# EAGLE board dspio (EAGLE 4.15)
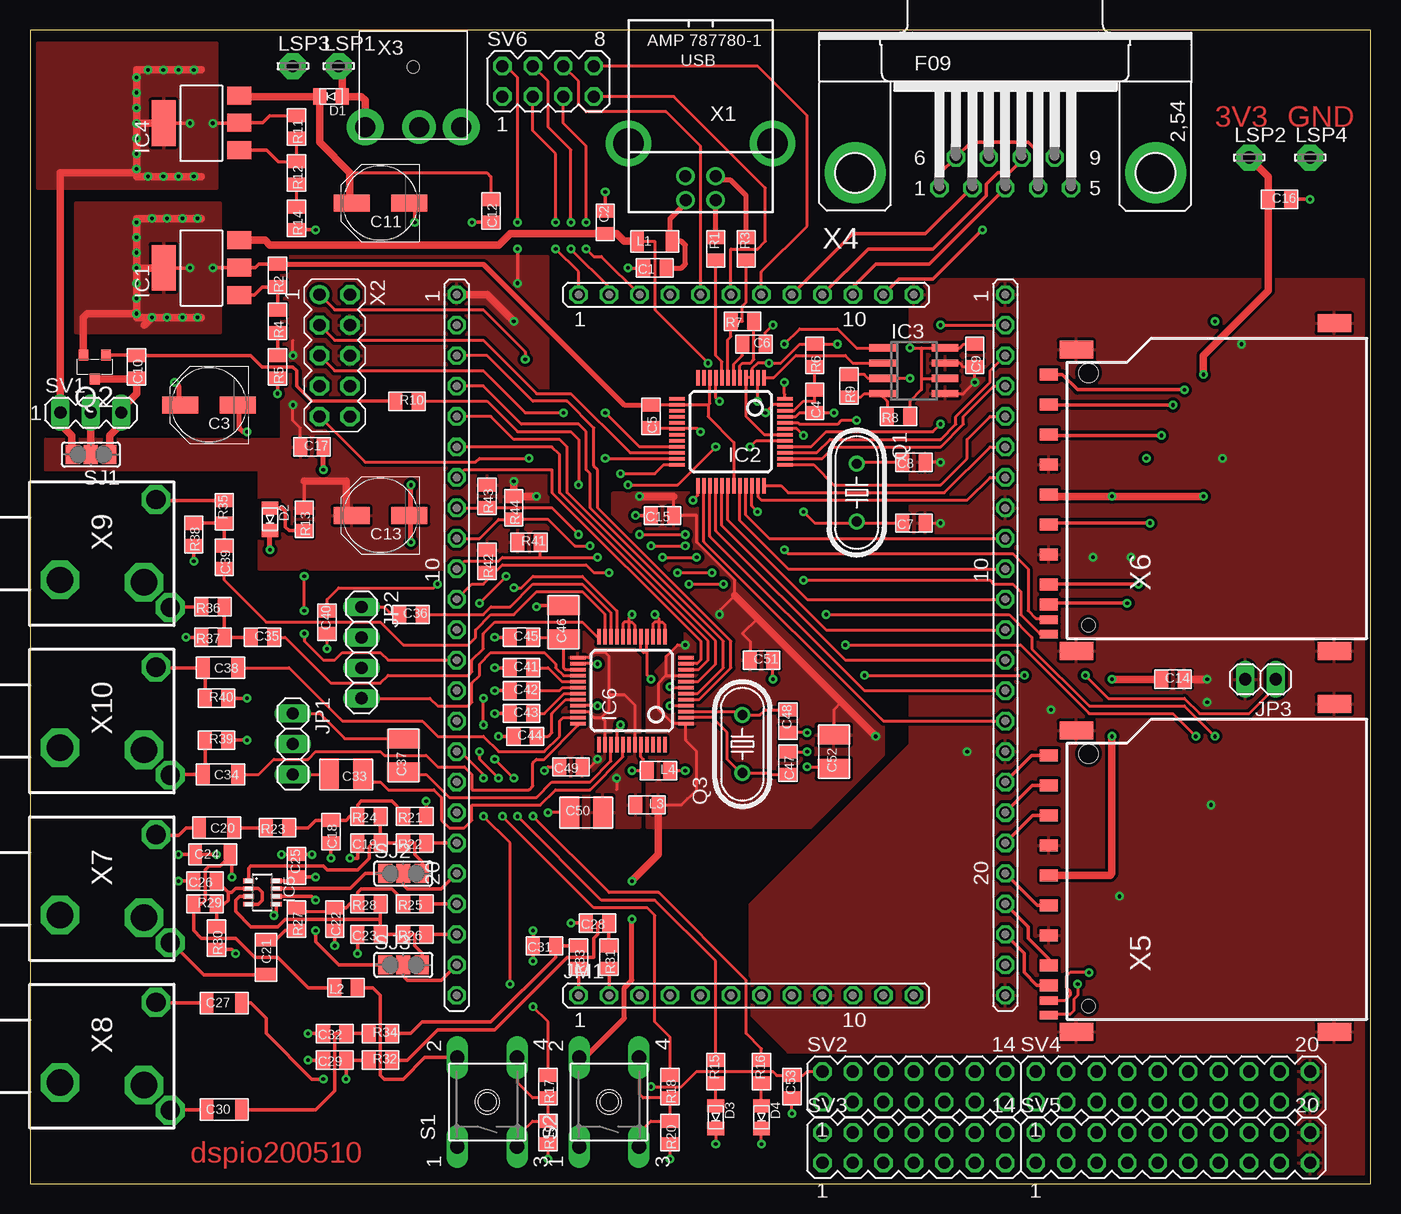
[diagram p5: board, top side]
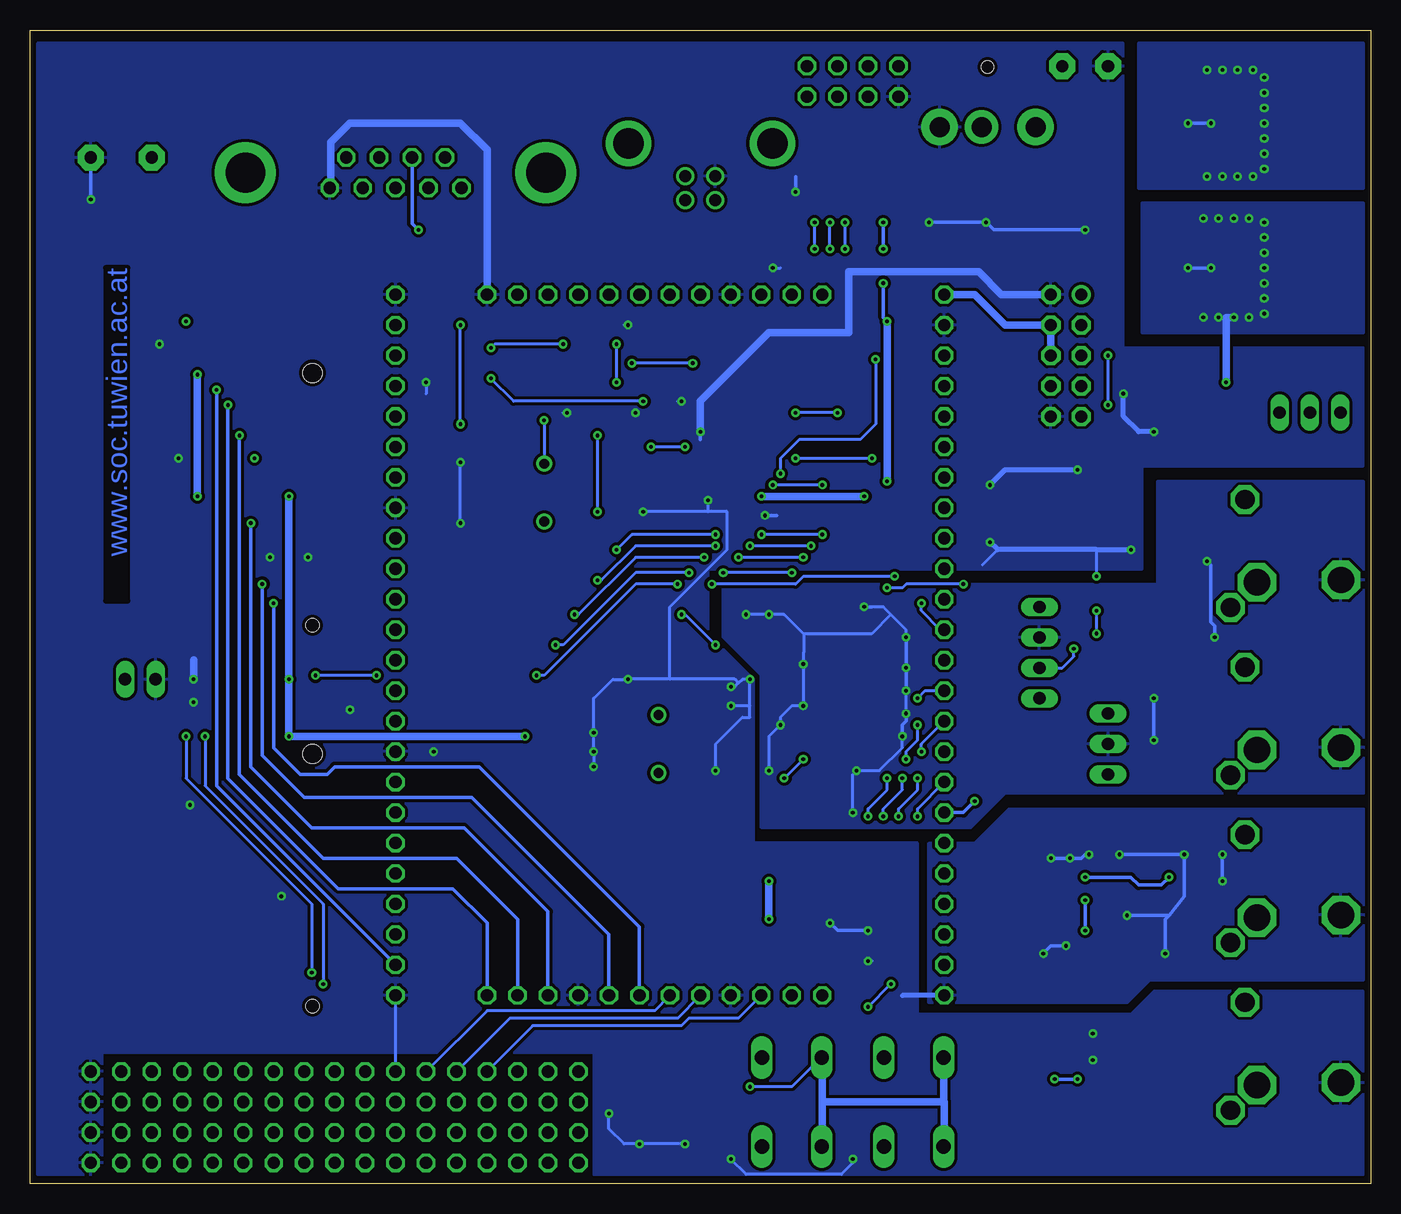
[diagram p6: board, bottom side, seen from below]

Size 111.74 x 96.19 mm. Coordinates in mm from the lower left corner, seen from the top.
Outline: 0,0 111.74,0 111.74,96.19 0,96.19 0,0
Copper layers (1*16): Top 0.035mm / dielectric 1.5mm / Bottom 0.035mm
Design rules "default": minimum track width 7mil, minimum drill 12mil, track to track 7mil, track to pad 8mil, pad to pad 8mil, via to via 8mil, smd to smd 8mil, copper to edge 12mil, drill to drill 8mil, minimum pad ring 10mil, minimum via ring 8mil, stop-mask expansion 4mil, vias tented up to drill 0mil, thermal gap 10mil

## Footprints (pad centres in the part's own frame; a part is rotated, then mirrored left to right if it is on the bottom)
0805 = smd 1.092 x 1.397: 1 -0.94,0; 2 0.94,0
PANASONIC_D = smd 3 x 1.4: + 2.4,0; - -2.4,0
1206 = smd 1.143 x 1.702: 1 -1.473,0; 2 1.473,0
1210 = smd 1.6 x 2.7: 1 -1.4,0; 2 1.4,0
D0805 = smd 1.092 x 1.397: 1 -0.94,0; 2 0.94,0
SOT223 = smd 1.499 x 2.007: 1 -2.261,-3.15; 2 0.025,-3.15; 3 2.311,-3.15 | smd 3.81 x 2.007: 4 0,3.15
LQFP = smd 0.279 x 1.27: 1 -2.75,-4.5; 2 -2.25,-4.5; 3 -1.75,-4.5; 4 -1.25,-4.5; 5 -0.75,-4.5; 6 -0.25,-4.5; 7 0.25,-4.5; 8 0.75,-4.5; 9 1.25,-4.5; 10 1.75,-4.5; 11 2.25,-4.5; 12 2.75,-4.5; 25 2.75,4.5; 26 2.25,4.5; 27 1.75,4.5; 28 1.25,4.5; 29 0.75,4.5; 30 0.25,4.5; 31 -0.25,4.5; 32 -0.75,4.5; 33 -1.25,4.5; 34 -1.75,4.5; 35 -2.25,4.5; 36 -2.75,4.5 | smd 1.27 x 0.279: 13 4.5,-2.75; 14 4.5,-2.25; 15 4.5,-1.75; 16 4.5,-1.25; 17 4.5,-0.75; 18 4.5,-0.25; 19 4.5,0.25; 20 4.5,0.75; 21 4.5,1.25; 22 4.5,1.75; 23 4.5,2.25; 24 4.5,2.75; 37 -4.5,2.75; 38 -4.5,2.25; 39 -4.5,1.75; 40 -4.5,1.25; 41 -4.5,0.75; 42 -4.5,0.25; 43 -4.5,-0.25; 44 -4.5,-0.75; 45 -4.5,-1.25; 46 -4.5,-1.75; 47 -4.5,-2.25; 48 -4.5,-2.75
SO-08 = smd 0.6 x 2.2: 1 -1.905,-2.6; 2 -0.635,-2.6; 3 0.635,-2.6; 4 1.905,-2.6; 5 1.905,2.6; 6 0.635,2.6; 7 -0.635,2.6; 8 -1.905,2.6
SOT23-8 = smd 0.4 x 0.9: 1 -0.975,-1.15; 2 -0.325,-1.15; 3 0.325,-1.15; 4 0.975,-1.15; 5 0.975,1.15; 6 0.325,1.15; 7 -0.325,1.15; 8 -0.975,1.15
QFP48 = smd 0.279 x 1.27: 1 -2.75,-4.5; 2 -2.25,-4.5; 3 -1.75,-4.5; 4 -1.25,-4.5; 5 -0.75,-4.5; 6 -0.25,-4.5; 7 0.25,-4.5; 8 0.75,-4.5; 9 1.25,-4.5; 10 1.75,-4.5; 11 2.25,-4.5; 12 2.75,-4.5; 25 2.75,4.5; 26 2.25,4.5; 27 1.75,4.5; 28 1.25,4.5; 29 0.75,4.5; 30 0.25,4.5; 31 -0.25,4.5; 32 -0.75,4.5; 33 -1.25,4.5; 34 -1.75,4.5; 35 -2.25,4.5; 36 -2.75,4.5 | smd 1.27 x 0.279: 13 4.5,-2.75; 14 4.5,-2.25; 15 4.5,-1.75; 16 4.5,-1.25; 17 4.5,-0.75; 18 4.5,-0.25; 19 4.5,0.25; 20 4.5,0.75; 21 4.5,1.25; 22 4.5,1.75; 23 4.5,2.25; 24 4.5,2.75; 37 -4.5,2.75; 38 -4.5,2.25; 39 -4.5,1.75; 40 -4.5,1.25; 41 -4.5,0.75; 42 -4.5,0.25; 43 -4.5,-0.25; 44 -4.5,-0.75; 45 -4.5,-1.25; 46 -4.5,-1.75; 47 -4.5,-2.25; 48 -4.5,-2.75
JOPMODULE = drill 1.016 octagon: 1 0,58.42; 2 0,55.88; 3 0,53.34; 4 0,50.8; 5 0,48.26; 6 0,45.72; 7 0,43.18; 8 0,40.64; 9 0,38.1; 10 0,35.56; 11 0,33.02; 12 0,30.48; 13 0,27.94; 14 0,25.4; 15 0,22.86; 16 0,20.32; 17 0,17.78; 18 0,15.24; 19 0,12.7; 20 0,10.16; 21 0,7.62; 22 0,5.08; 23 0,2.54; 24 0,0; 25 10.16,0; 26 12.7,0; 27 15.24,0; 28 17.78,0; 29 20.32,0; 30 22.86,0; 31 25.4,0; 32 27.94,0; 33 30.48,0; 34 33.02,0; 35 35.56,0; 36 38.1,0; 37 45.72,58.42; 38 45.72,55.88; 39 45.72,53.34; 40 45.72,50.8; 41 45.72,48.26; 42 45.72,45.72; 43 45.72,43.18; 44 45.72,40.64; 45 45.72,38.1; 46 45.72,35.56; 47 45.72,33.02; 48 45.72,30.48; 49 45.72,27.94; 50 45.72,25.4; 51 45.72,22.86; 52 45.72,20.32; 53 45.72,17.78; 54 45.72,15.24; 55 45.72,12.7; 56 45.72,10.16; 57 45.72,7.62; 58 45.72,5.08; 59 45.72,2.54; 60 45.72,0; 61 10.16,58.42; 62 12.7,58.42; 63 15.24,58.42; 64 17.78,58.42; 65 20.32,58.42; 66 22.86,58.42; 67 25.4,58.42; 68 27.94,58.42; 69 30.48,58.42; 70 33.02,58.42; 71 35.56,58.42; 72 38.1,58.42
1X03 = drill 1.016 long: 1 -2.54,0; 2 0,0; 3 2.54,0
1X04 = drill 1.016 long: 1 -3.81,0; 2 -1.27,0; 3 1.27,0; 4 3.81,0
1X02 = drill 1.016 long: 1 -1.27,0; 2 1.27,0
LSP10 = drill 1.016 pad 2.159 octagon: MP 0,0
HC49U-V = drill 0.813 round: 1 -2.413,0; 2 2.413,0
MICRO3 = smd 0.8 x 0.9: 1 -0.95,-1; 2 0.95,-1; 3 0,1
BTN = drill 1.194 long: 1 -3.708,2.489; 2 3.708,2.489; 3 -3.708,-2.489; 4 3.708,-2.489
SJ_2 = smd 1.168 x 1.6: 1 -1.524,0; 2 0,0; 3 1.524,0
MA03-1 = drill 1.016 long: 1 -2.54,0; 2 0,0; 3 2.54,0
MA07-2 = drill 1.016 octagon: 1 -7.62,-1.27; 2 -7.62,1.27; 3 -5.08,-1.27; 4 -5.08,1.27; 5 -2.54,-1.27; 6 -2.54,1.27; 7 0,-1.27; 8 0,1.27; 9 2.54,-1.27; 10 2.54,1.27; 11 5.08,-1.27; 12 5.08,1.27; 13 7.62,-1.27; 14 7.62,1.27
MA10-2 = drill 1.016 octagon: 1 -11.43,-1.27; 2 -11.43,1.27; 3 -8.89,-1.27; 4 -8.89,1.27; 5 -6.35,-1.27; 6 -6.35,1.27; 7 -3.81,-1.27; 8 -3.81,1.27; 9 -1.27,-1.27; 10 -1.27,1.27; 11 1.27,-1.27; 12 1.27,1.27; 13 3.81,-1.27; 14 3.81,1.27; 15 6.35,-1.27; 16 6.35,1.27; 17 8.89,-1.27; 18 8.89,1.27; 19 11.43,-1.27; 20 11.43,1.27
MA04-2 = drill 1.016 octagon: 1 -3.81,-1.27; 2 -3.81,1.27; 3 -1.27,-1.27; 4 -1.27,1.27; 5 1.27,-1.27; 6 1.27,1.27; 7 3.81,-1.27; 8 3.81,1.27
USB-B = drill 1 round: 1 1.25,14.99; 2 -1.25,14.99; 3 -1.25,12.99; 4 1.25,12.99 | drill 2.54 pad 3.81 round: P$1 -6,10.25; P$2 6,10.25
BYTEBLST = drill 1.016 pad 1.6 round: 1 -5.08,-1.27 | drill 1.016 pad 1.6 octagon: 2 -5.08,1.27; 3 -2.54,-1.27; 4 -2.54,1.27; 5 0,-1.27; 6 0,1.27; 7 2.54,-1.27; 8 2.54,1.27; 9 5.08,-1.27; 10 5.08,1.27
DCCON = drill 1.676 pad 3.048 round: 1 0,0; 3 8,0 | drill 1.676 pad 2.794 round: 2 4.5,0 | hole 1.016: 4,5
F09HP = drill 1.016 octagon: 1 -5.486,-1.27; 2 -2.743,-1.27; 3 0,-1.27; 4 2.743,-1.27; 5 5.486,-1.27; 6 -4.115,1.27; 7 -1.372,1.27; 8 1.372,1.27; 9 4.115,1.27 | drill 3.302 pad 5.08 round: G1 -12.522,0; G2 12.522,0
SD-CARD = smd 1 x 1.5: 1 -2.5,0.5; 2 -5,0.5; 3 -7.5,0.5; 4 -10,0.5; 5 -12.5,0.5; 6 -15,0.5; 7 -17.5,0.5; 8 -19.15,0.5; 9 0,0.5 | smd 0.7 x 1.5: CDI -20.45,0.5; WP -21.65,0.5 | smd 1.5 x 2.8: G1 -23.025,-1.8; G2 2.075,-1.8; G3 -23.025,-23.3; G4 4.275,-23.3 | hole 1.6: 0.125,-2.8 | hole 1.1: -20.9,-2.8
STEREO35 = drill 2.2 octagon: C 2.2,2.5; N 2.4,9.5 | drill 1.6 octagon: L -4.5,10.5; R 4.5,11.7

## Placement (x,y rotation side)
C1  10n  [0805]  52.06,76.35 0 top
C2  100n  [0805]  47.94,80.16 270 top
C3  100u/6V3  [PANASONIC_D]  14.92,64.92 180 top
C4  100n  [0805]  65.4,65.24 90 top
C5  100n  [0805]  51.75,63.97 90 top
C6  100n  [0805]  60.32,70 180 top
C7  22p  [0805]  73.66,55.08 0 top
C8  22p  [0805]  73.66,60.16 0 top
C9  100n  [0805]  78.73,69.05 90 top
C10  100n  [0805]  8.89,68.1 90 top
C11  47u/16V  [PANASONIC_D]  29.21,81.75 180 top
C12  100n  [0805]  38.41,81.11 90 top
C13  100u/6V3  [PANASONIC_D]  29.21,55.72 180 top
C14  100n  [0805]  95.24,42.06 180 top
C15  100n  [0805]  52.7,55.72 0 top
C16  10n  [0805]  104.13,82.07 180 top
C17  10n  [0805]  23.49,61.43 180 top
C18  470p  [0805]  25.08,29.36 90 top
C19  47p  [0805]  28.25,28.41 0 top
C20  2u2  [1206]  15.55,29.68 180 top
C21  2u2  [1206]  19.68,18.88 270 top
C22  470p  [0805]  25.39,22.06 90 top
C23  47p  [0805]  28.25,20.79 0 top
C24  2u2  [1206]  15.24,27.46 0 top
C25  100n  [0805]  22.22,26.51 270 top
C26  100n  [0805]  14.6,25.23 0 top
C27  2u2  [1206]  16.19,15.08 0 top
C28  4n7  [0805]  47.3,21.74 0 top
C29  4n7  [0805]  25.39,10.31 0 top
C30  2u2  [1206]  16.19,6.19 0 top
C31  4n7  [0805]  42.86,19.84 0 top
C32  4n7  [0805]  25.39,12.53 0 top
C33  10u  [1210]  26.35,34.12 180 top
C34  2u2  [1206]  15.87,34.12 180 top
C35  470n  [0805]  19.36,45.55 180 top
C36  470n  [0805]  31.75,47.46 180 top
C37  10u  [1210]  31.11,35.71 90 top
C38  2u2  [1206]  15.87,43.02 180 top
C39  470n  [0805]  16.19,52.22 90 top
C40  470n  [0805]  24.76,46.83 270 top
C41  220p  [0805]  40.95,43.02 180 top
C42  220p  [0805]  40.95,41.11 180 top
C43  220p  [0805]  40.95,39.2 180 top
C44  220p  [0805]  41.27,37.3 180 top
C45  100n  [0805]  40.95,45.55 180 top
C46  10u  [1210]  44.44,46.83 90 top
C47  22p  [0805]  63.18,35.08 90 top
C48  22p  [0805]  63.18,38.57 270 top
C49  10n  [0805]  45.08,34.76 0 top
C50  10u  [1210]  46.35,30.95 0 top
C51  10n  [0805]  60.95,43.65 180 top
C52  10u  [1210]  66.99,36.03 90 top
C53  100n  [0805]  63.49,8.09 270 top
D1  BAT254  [D0805]  25.08,90.64 180 top
D2  LED0805  [D0805]  20,55.4 270 top
D3  LED0805  [D0805]  57.14,5.55 270 top
D4  LED0805  [D0805]  60.95,5.55 270 top
IC1  LM317SMD  [SOT223]  14.28,76.35 90 top
IC2  FT2232C  [LQFP]  58.41,62.7 180 top
IC3  93LCS56SN  [SO-08]  73.66,67.78 270 top
IC4  LM317SMD  [SOT223]  14.28,88.42 90 top
IC5  TLV3502  [SOT23-8]  19.36,24.28 270 top
IC6  AD1981  [QFP48]  50.16,41.11 90 top
JM1  JOPMODULE  [JOPMODULE]  35.56,15.71 0 top
JP1  [1X03]  21.9,36.66 270 top
JP2  [1X04]  27.62,44.29 270 top
JP3  [1X02]  102.55,42.06 180 top
L1  1000R  [1206]  52.06,78.57 0 top
L2  600R  [0805]  26.35,16.34 0 top
L3  600R  [0805]  51.43,31.59 180 top
L4  600R  [0805]  52.38,34.44 180 top
LSP1  LSP10  [LSP10]  25.71,93.18 0 top
LSP2  LSP10  [LSP10]  101.59,85.56 0 top
LSP3  LSP10  [LSP10]  21.9,93.18 0 top
LSP4  LSP10  [LSP10]  106.67,85.56 0 top
Q1  6MHz  [HC49U-V]  68.89,57.62 270 top
Q2  IRLML6402  [MICRO3]  5.39,68.1 180 top
Q3  24.576MHz  [HC49U-V]  59.37,36.66 90 top
R1  27R  [0805]  57.14,77.94 270 top
R2  1k  [0805]  20.63,75.72 90 top
R3  27R  [0805]  59.69,77.94 270 top
R4  100R  [0805]  20.63,71.91 90 top
R5  1k5  [0805]  20.63,68.1 90 top
R6  470R  [0805]  65.4,69.05 90 top
R7  1k5  [0805]  59.37,71.91 0 top
R8  10k  [0805]  72.38,63.97 0 top
R9  2k2  [0805]  68.26,66.51 90 top
R10  1k  [0805]  31.43,65.24 180 top
R11  1k  [0805]  22.22,88.1 90 top
R12  100R  [0805]  22.22,84.29 90 top
R13  680R  [0805]  22.86,55.4 90 top
R14  1k5  [0805]  22.22,80.48 90 top
R15  680R  [0805]  57.14,9.36 270 top
R16  680R  [0805]  60.95,9.36 270 top
R17  10k  [0805]  43.17,8.09 90 top
R18  10k  [0805]  53.33,8.09 90 top
R19  10k  [0805]  43.17,4.28 90 top
R20  10k  [0805]  53.33,4.28 90 top
R21  10k  [0805]  32.06,30.63 0 top
R22  100k  [0805]  32.06,28.41 0 top
R23  10k  [0805]  20.63,29.68 0 top
R24  100k  [0805]  28.25,30.63 0 top
R25  10k  [0805]  32.06,23.33 0 top
R26  100k  [0805]  32.06,20.79 0 top
R27  10k  [0805]  22.22,22.06 90 top
R28  100k  [0805]  28.25,23.33 0 top
R29  1k  [0805]  14.6,23.33 180 top
R30  1k  [0805]  15.55,20.47 90 top
R31  1k  [0805]  48.25,18.88 90 top
R32  1k  [0805]  29.21,10.31 180 top
R33  1k  [0805]  45.72,18.88 90 top
R34  1k  [0805]  29.21,12.53 180 top
R35  4k7  [0805]  16.19,56.03 270 top
R36  4k7  [0805]  15.24,48.09 0 top
R37  4k7  [0805]  15.24,45.55 0 top
R38  4k7  [0805]  13.65,54.13 90 top
R39  47k  [0805]  15.55,36.98 180 top
R40  47k  [0805]  15.55,40.48 180 top
R41  10k  [0805]  41.59,53.49 180 top
R42  10k  [0805]  38.09,51.91 90 top
R43  10k  [0805]  38.09,57.3 90 top
R44  10k  [0805]  40.32,56.35 90 top
S1  BTN  [BTN]  38.09,6.82 90 top
S2  BTN  [BTN]  48.25,6.82 90 top
SJ1  [SJ_2]  5.07,60.79 180 top
SJ2  [SJ_2]  31.11,25.87 0 top
SJ3  [SJ_2]  31.11,18.25 0 top
SV1  [MA03-1]  5.07,64.29 0 top
SV2  [MA07-2]  73.66,8.09 0 top
SV3  [MA07-2]  73.66,3.01 0 top
SV4  [MA10-2]  95.24,8.09 0 top
SV5  [MA10-2]  95.24,3.01 0 top
SV6  [MA04-2]  43.17,91.91 0 top
X1  USB Connector  [USB-B]  55.88,96.99 180 top
X2  BYTEBLST  [BYTEBLST]  25.39,69.05 270 top
X3  [DCCON]  27.93,88.1 0 top
X4  [F09HP]  81.27,84.29 0 top
X5  SD-CARD  [SD-CARD]  85.4,35.71 90 top
X6  SD-CARD  [SD-CARD]  85.4,67.46 90 top
X7  STEREO35  [STEREO35]  0,24.6 270 top
X8  STEREO35  [STEREO35]  0,10.63 270 top
X9  STEREO35  [STEREO35]  0,52.54 270 top
X10  STEREO35  [STEREO35]  0,38.57 270 top

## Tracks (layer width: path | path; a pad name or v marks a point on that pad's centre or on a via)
+5V  (via drill 0.3)
  Top 0.254: C9.2 78.73,70 77.78,70 77.47,69.68 IC3.8 74.29,69.68 | 74.29,69.68 74.29,67.14 | 74.29,67.14 IC3.6 | R8.2 73.33,65.23 74.29,66.19 74.29,67.14 | v67.3,70 67.29,69.99 R6.2 65.4,70 64.13,70 62.54,68.41 v61.59,68.41 60.64,68.41 60.16,67.94 IC2.3 59.74,67.2 59.69,67.14 59.66,67.16 IC2.4 59.66,63.99 61.2,62.45 IC2.42 | v73.34,69.68 74.29,69.68 | L1.1 52.06,78.57 52.06,72.86 v56.51,68.41
  Top 0.61: IC1.3 19.59,78.66 20,78.26 39.05,78.26 40,79.21 46.35,79.21 C2.2 48.88,79.22 49.52,78.57 L1.1
  Bottom 0.254: v67.3,70 73.02,70 v73.34,69.68 | v56.51,68.41 v61.59,68.41
A_CD  (via drill 0.3)
  Top 0.254: JM1.10 36.19,51.91 39.05,51.91 39.36,52.22 42.54,52.22 | R41.1 42.54,53.18 42.54,52.22 | 42.54,52.22 v47.3,52.22 | v52.7,52.22 v55.56,52.22 | v66.35,47.46 81.59,47.46 83.5,45.55 83.5,44.6 88.26,39.84 96.2,39.84 v98.74,37.3 | X5.CDI 86.22,15.26 86.67,15.71 86.67,16.03 86.36,16.34 86.36,17.3 86.67,17.62 v88.26,17.62
  Bottom 0.254: v47.3,52.22 v52.7,52.22 | v55.56,52.22 61.27,52.22 66.03,47.46 v66.35,47.46 | v88.26,17.62 88.26,23.33 98.74,33.81 v98.74,37.3
A_CLK
  Top 0.305: X5.5 83.93,23.21 JM1.56
A_CMD
  Top 0.305: X5.2 83.58,30.71 JM1.55
A_D0
  Top 0.305: X5.7 84.9,18.75 83.18,20.47 83.18,21.42 JM1.57
A_D1
  Top 0.305: X5.8 83.91,16.56 82.86,17.62 82.86,19.2 JM1.58
A_D2
  Top 0.305: X5.9 83.5,35.71 JM1.53
A_D3
  Top 0.305: X5.1 83.54,33.21 JM1.54
A_WP  (via drill 0.3)
  Top 0.254: JM1.11 36.83,50 37.78,50 38.09,50.32 R42.1 38.74,50.97 39.36,51.59 46.35,51.59 46.98,50.95 v48.25,50.95 | v67.94,44.92 82.55,44.92 88.26,39.2 95.24,39.2 v97.15,37.3 | v53.97,50.95 v56.83,50.95 | v87.31,16.66 87.31,15.71 86.99,15.39 86.99,14.44 86.67,14.12 85.4,14.12 X5.WP
  Bottom 0.254: v67.94,44.92 67.3,44.92 61.27,50.95 v56.83,50.95 | v48.25,50.95 v53.97,50.95 | v97.15,37.3 97.15,33.17 87.31,23.33 v87.31,16.66
AC97_BCLK
  Top 0.254: JM1.4 37.78,66.51 40.95,63.34 45.72,63.34 46.35,62.7 46.35,59.52 46.67,59.21 46.67,56.35 57.78,45.24 57.78,43.02 55.62,40.86 IC6.6
AC97_NRES
  Top 0.254: JM1.7 36.19,59.52 43.49,59.52 43.49,57.62 55.88,45.24 55.88,43.65 55.58,43.36 IC6.11
AC97_SDI
  Top 0.254: JM1.5 38.41,63.97 40.32,62.07 44.13,62.07 44.76,61.43 44.76,57.62 57.14,45.24 57.14,43.33 55.67,41.86 IC6.8
AC97_SDO
  Top 0.254: JM1.3 38.09,69.05 41.91,65.24 44.76,65.24 46.98,63.02 46.98,59.84 47.3,59.52 47.3,56.35 58.41,45.24 58.41,43.02 55.76,40.36 IC6.5
AC97_SYN
  Top 0.254: JM1.6 43.49,61.43 44.13,60.79 44.13,57.62 56.51,45.24 56.51,43.65 55.72,42.86 IC6.10
AC97_VREF
  Top 0.254: IC6.28 44.47,42.36 43.81,43.02 43.81,43.33 42.86,44.29 38.41,44.29 37.46,43.33 37.46,42.38 36.83,41.75 36.83,40.16 36.51,39.84 33.97,39.84 33.33,40.48 JP2.4
AGND  (via drill 0.3)
  Top 0.254: IC6.33 47.28,39.86 v47.3,39.84 | 49.91,46.83 IC6.19 | 49.91,46.83 49.91,47.21 v50.16,47.46 | 49.91,46.83 49.52,46.83 49.41,46.71 IC6.20 | 49.91,46.83 50.16,46.83 50.41,46.58 IC6.18 | 52.41,46.83 52.41,47.12 v52.06,47.46 | 52.41,46.83 IC6.14 | 52.41,46.83 52.06,46.83 51.91,46.67 IC6.15 | 52.41,46.83 52.7,46.83 52.91,46.62 IC6.13 | IC6.40 48.91,37.95 v49.21,38.25 | v50.16,34.44 51.43,34.44 | IC6.26 47.27,43.36 v47.3,43.33 | IC6.44 50.91,35.6 51.11,35.4 51.11,34.76 51.43,34.44 | 51.43,34.44 L4.2 | C49.1 43.17,34.76 v42.86,34.44 | C50.1 v43.17,30.95
  Top 0.305: v38.73,43.02 C41.2 | v38.73,41.11 C42.2 | v38.73,39.2 C43.2 | v39.05,37.3 C44.2 | v38.73,45.55 C45.2 | C46.2 42.35,48.23 v42.22,48.09 | v18.09,40.48 R40.1 | R39.1 v18.09,36.98 | R37.1 v13.01,45.55 | v13.65,51.91 R38.1
  Bottom 0.254: v52.06,47.46 v50.16,47.46 48.89,47.46 47.27,45.84 | v38.73,39.2 v38.73,41.11 | v38.73,45.55 38.73,46.19 40,47.46 | 40,47.46 40.64,48.09 41.59,48.09 | 47.27,45.84 41.61,45.84 40,47.46 | v50.16,34.44 50.16,37.3 v49.21,38.25 49.21,38.89 48.25,39.84 v47.3,39.84 v47.3,43.33 47.3,44.29 47.27,44.31 47.27,45.84 | v39.05,37.3 39.05,36.35 40.95,34.44 v42.86,34.44 43.17,34.12 v43.17,30.95
  Bottom 0.305: v38.73,41.11 v38.73,43.02 v38.73,45.55 | v39.05,37.3 39.05,38.25 38.73,38.57 v38.73,39.2 | 41.59,48.09 41.91,48.09 | v18.09,36.98 v18.09,40.48 | v13.01,45.55 13.01,46.51 13.33,46.83 13.33,51.59 v13.65,51.91
  pour Bottom (isolate 0.254): 50.8,29.68 50.8,42.38 53.97,45.55 53.97,50 17.78,50 17.78,58.57 0.63,58.57 0.63,32.54 30.47,32.54 33.33,29.68
AL
  Top 0.305: C20.2 13.01,29.68 12.38,29.05 10.47,29.05 10.5,29.07 X7.L
AOUTL
  Top 0.305: JM1.26 R31.1
AOUTR
  Top 0.305: JM1.25 R33.1
AR
  Top 0.305: X7.R 11.74,20.16 14.49,17.41 C21.2
AVDD  (via drill 0.3)
  Top 0.254: IC6.25 46.56,43.86 46.98,44.29 47.94,44.29 48.25,43.97 48.25,40.79 | 48.25,40.79 48.25,39.52 47.62,38.89 | 47.62,38.89 46.98,38.89 46.51,39.36 IC6.34 | IC6.38 47.91,38.6 47.62,38.89 | IC6.43 50.41,39.91 49.52,40.79 48.25,40.79 | C49.2 46.67,34.76 v47.3,35.4 | v48.89,33.81 48.89,32.86
  Bottom 0.254: v47.3,35.4 v48.89,33.81
  pour Top (isolate 0.254): 50.8,46.83 50.8,29.68 44.13,29.68 44.13,46.83
B3
  Bottom 0.254: JM1.27 52.7,13.8 56.83,13.8 57.46,13.17 69.84,13.17 SV2.8
B4
  Bottom 0.254: JM1.29 57.78,13.8 71.75,13.8 SV2.10
B5
  Bottom 0.254: JM1.30 59.69,14.44 73.66,14.44 SV2.12
B_CD  (via drill 0.3)
  Top 0.254: JM1.8 R43.1 43.48,56.36 v45.72,54.13 | v50.8,54.13 v54.61,54.13 | v62.86,52.86 63.18,52.54 81.91,52.54 83.18,51.27 83.18,47.78 83.81,47.14 85.4,47.14 X6.CDI
  Bottom 0.254: v54.61,54.13 61.59,54.13 v62.86,52.86 | v45.72,54.13 v50.8,54.13
B_CLK  (via drill 0.3)
  Top 0.305: X6.5 84.97,54.96 85.08,55.08 v93.34,55.08
  Bottom 0.305: JM1.34 68.58,22.7 75.56,29.68 88.26,29.68 93.34,34.76 v93.34,55.08
B_CMD  (via drill 0.3)
  Top 0.305: X6.2 85,62.46 85.08,62.38 v94.29,62.38
  Bottom 0.305: JM1.35 71.11,22.06 76.19,27.14 87.31,27.14 94.29,34.12 v94.29,62.38
B_D0  (via drill 0.3)
  Top 0.305: X6.7 85.05,49.96 85.08,50 v92.39,50
  Bottom 0.305: JM1.32 63.49,20.79 74.92,32.22 88.89,32.22 92.39,35.71 v92.39,50
B_D1  (via drill 0.3)
  Top 0.305: X6.8 84.87,48.31 84.77,48.41 v91.44,48.41
  Bottom 0.305: JM1.31 60.95,21.42 74.29,34.76 86.36,34.76 86.99,34.12 89.21,34.12 91.44,36.35 v91.44,48.41
B_D2  (via drill 0.3)
  Top 0.305: v96.2,66.19 87.31,66.19 86.04,67.46 X6.9
  Bottom 0.305: JM1.59 96.2,33.17 v96.2,66.19
B_D3  (via drill 0.3)
  Top 0.305: X6.1 85.05,64.96 85.08,64.92 v95.24,64.92
  Bottom 0.305: JM1.36 73.66,21.74 76.51,24.6 86.04,24.6 95.24,33.81 v95.24,64.92
B_WP  (via drill 0.3)
  Top 0.254: JM1.9 37.46,53.81 39.05,55.4 40.32,55.4 R44.1 43.16,55.41 45.4,53.18 v46.67,53.18 | v51.75,53.18 v54.61,53.18 | v64.45,50.32 80,50.32 80.32,50 81.91,50 82.55,49.37 82.55,47.46 84.13,45.87 85.4,45.87 X6.WP
  Bottom 0.254: v46.67,53.18 v51.75,53.18 | v54.61,53.18 61.27,53.18 64.13,50.32 v64.45,50.32
BTN0  (via drill 0.3)
  Top 0.254: R17.2 43.17,13.49 v41.91,14.76 | v40,16.66 40,28.41 v37.78,30.63
  Bottom 0.254: JM1.17 37.78,31.27 v37.78,30.63 | v41.91,14.76 v40,16.66
BTN1  (via drill 0.3)
  Top 0.254: JM1.16 35.87,36.03 37.78,34.12 v37.78,33.81 | R18.2 53.33,12.22 52.06,13.49 52.06,22.38 51.43,23.01 46.98,23.01 v39.36,30.63
  Bottom 0.254: v37.78,33.81 37.78,32.86 39.36,31.27 v39.36,30.63
COMPOL
  Top 0.305: IC5.7 26.67,24.61 27.93,25.87 SJ2.1
COMPOL1  (via drill 0.3)
  Top 0.305: IC5.6 23.5,23.96 v23.81,23.65 | v23.81,21.11 23.81,20.16 25.71,18.25 SJ3.1
  Bottom 0.305: v23.81,21.11 v23.81,23.65
GND  (via drill 0.3)
  Top 0.254: IC2.45 63.79,63.95 64.13,64.29 65.4,64.29 | 78.73,68.1 v78.73,66.83 77.78,65.88 IC3.5 | IC3.7 77.47,68.41 77.78,68.1 78.73,68.1 | 78.73,68.1 C9.1 | IC2.25 55.66,57.41 v55.24,56.99 | IC2.34 60.16,56.51 v60.64,56.03 | C6.1 61.26,70.94 v61.91,71.59 | IC2.9 57.16,65.54 v57.46,65.24 | v49.84,76.35 C1.1 | IC2.47 61.94,64.95 v61.27,64.29 | v55.88,62.7 55.62,62.95 IC2.18 51.81,62.95 51.75,63.02 C5.1 | C8.2 74.59,60.17 v75.88,60.16 | C7.2 v75.88,55.08 | IC6.16 51.41,44.62 51.43,44.6 51.43,44.29 | 51.43,44.29 51.43,42.38 v51.75,42.06 | 51.43,44.29 51.11,44.29 50.91,44.49 IC6.17 | L4.1 v54.61,34.44 | IC6.7 53.4,41.36 v53.33,41.43 | IC6.4 53.36,39.86 v53.33,39.84 | C48.2 63.18,37.62 v64.77,37.62 | C47.2 64.75,36.02 v64.77,36.03 | C52.1 66.99,34.76 v64.77,34.76 | C51.1 61.89,42.08 v61.91,42.06 | JM1.13 29.84,43.65 29.21,44.29 26.03,44.29 25.39,43.65 24.44,43.65 22.86,45.24 v22.86,45.87 | v22.86,47.78 v22.86,50.63 | v43.17,2.06 R19.1 | v53.33,2.06 R20.1 | D3.2 v57.14,3.33 | v60.95,3.33 D4.2 | v63.49,5.87 C53.2 | 65.4,64.29 v66.99,64.29 | 65.4,64.29 C4.1
  Top 0.305: C2.1 v47.94,82.7 | v20.63,65.88 R5.1 | v50.48,55.72 C15.1 | R14.1 v23.79,79.54 v23.81,79.53 | C11.- 32.2,81.57 32.06,81.43 v32.06,80.16 | C12.1 36.84,80.17 v36.83,80.16 | C16.1 v106.67,82.07 | v25.39,19.84 C22.1 | C23.1 27.3,20.79 v27.3,19.2 | v25.08,27.14 C18.1 | C19.1 27.3,28.41 27.3,27.14 v26.67,27.14 | v20.95,27.46 20.96,27.45 C25.1 23.48,27.45 v23.49,27.46 | v15.55,27.46 C24.1 v12.38,27.46 | IC5.5 20.51,22.5 v20.32,22.38 | R30.1 16.81,19.53 v17.14,19.2 | v12.38,25.23 C26.1 | v41.91,18.57 41.92,18.58 C31.1 41.92,21.09 v41.91,21.11 | v45.08,21.74 C28.1 | C32.1 v23.17,12.53 | C29.1 v23.17,10.31
  Top 0.406: v20,52.86 D2.2 | C17.1 24.43,59.85 v24.44,59.52 | v18.09,62.7 17.78,62.7 17.46,63.02 17.46,64.92 C3.- | 31.75,55.72 v31.75,58.26 | 31.75,55.72 C13.- | v31.75,53.49 31.75,55.72
  Top 0.61: C14.1 v98.1,42.06
  Bottom 0.254: v78.73,66.83 78.73,65.88 | 55.24,56.03 v55.24,56.99 | 55.24,56.03 v60.64,56.03 | v61.91,71.59 62.22,71.59 | v57.46,65.24 57.78,65.24 | v49.84,76.35 49.21,76.35 | v61.27,64.29 61.27,63.97 | v75.88,55.08 v75.88,60.16 | 31.11,52.86 32.38,51.59 | 51.75,39.84 51.75,38.89 52.38,38.89 54.61,36.66 v54.61,34.44 | 51.75,39.84 v51.75,42.06 52.38,42.06 52.7,41.75 | v53.33,41.43 53.02,41.43 52.7,41.75 | 51.75,39.84 v53.33,39.84 | v61.91,42.06 63.18,42.06 64.77,40.48 v64.77,37.62 v64.77,36.03 v64.77,34.76 | 58.41,42.08 53.03,42.08 52.7,41.75 | 58.41,42.08 61.89,42.08 | 55.24,56.03 53.65,56.03 53.65,52.86 58.41,48.09 58.41,42.08 | 58.41,42.08 58.41,42.06 | v22.86,45.87 v22.86,47.78 | v22.86,50.63 22.86,52.86 | v43.17,2.06 43.17,1.74 44.13,0.79 52.06,0.79 v53.33,2.06 | v57.14,3.33 v60.95,3.33 62.22,3.33 63.49,4.6 v63.49,5.87 | SV2.14 JM1.60 | v66.99,64.29 67.3,64.29
  Bottom 0.305: v47.94,82.7 47.94,83.97 | v55.88,62.7 55.88,62.07 | v50.48,55.72 49.52,55.72 | v23.81,79.53 31.43,79.53 v32.06,80.16 v36.83,80.16 | 106.67,85.88 LSP4.MP v106.67,82.07 | v25.39,19.84 26.67,19.84 v27.3,19.2 | v26.67,27.14 v25.08,27.14 24.13,27.14 23.81,27.46 v23.49,27.46 | v20.95,27.46 v15.55,27.46 15.55,23.96 16.82,22.38 | 16.82,22.38 v20.32,22.38 | v17.14,19.2 17.14,22.06 16.82,22.38 | v12.38,27.46 v12.38,25.23 | v41.91,18.57 41.59,18.57 | v41.91,21.11 44.44,21.11 v45.08,21.74
  Bottom 0.406: v31.75,53.49 31.11,52.86 22.86,52.86 v20,52.86 | v20.63,65.88 20.63,63.97 19.36,62.7 v18.09,62.7 | v24.44,59.52 30.47,59.52 v31.75,58.26 | JM1.24 39.05,15.71
  Bottom 0.61: JM1.72 73.66,86.19 75.88,88.42 85.08,88.42 86.67,86.83 86.67,83.02 X4.5 | v98.1,42.06 98.1,43.65 | X2.2 30.79,74.13 32.7,76.03 43.49,76.03 43.49,70.95 50.16,70.95 55.88,65.24 v55.88,62.7
  other vias: 100.96,70 99.37,60.48 91.75,52.22 88.58,52.22 98.1,40.16 85.08,39.52 78.1,36.03 98.42,31.59 90.8,23.96
  pour Top (isolate 0.254): 111.12,75.4 111.12,0.79 105.72,0.79 105.72,10.95 63.18,10.95 60,14.12 60,23.33 73.34,36.66 73.34,75.4
  pour Bottom (isolate 0.254): 0.63,59.84 0.63,69.68 20.63,69.68 20.63,95.08 111.12,95.08 111.12,0.79 105.72,0.79 105.72,10.95 64.77,10.95 64.77,0.79 0.63,0.79 0.63,16.03 18.09,16.03 20,14.12 37.78,14.12 37.78,28.41 51.43,28.41 51.43,42.06 54.29,44.92 55.24,44.92 55.24,51.27 19.04,51.27 19.04,59.84
  pour Bottom (isolate 0.254): 36.83,28.41 33.02,28.41 30.16,31.27 0.63,31.27 0.63,16.98 18.41,16.98 20.32,15.08 36.83,15.08
LED0  (via drill 0.3)
  Top 0.254: v37.46,36.03 37.46,35.4 v39.05,33.81 | v40.64,30.63 47.62,23.65 52.06,23.65 57.14,18.57 R15.1
  Bottom 0.254: JM1.15 37.46,36.66 v37.46,36.03 | v39.05,33.81 39.05,32.86 40.64,31.27 v40.64,30.63
LED1  (via drill 0.3)
  Top 0.254: v37.78,38.25 v37.78,40.48 | v40.32,33.81 v38.73,35.4 | R16.1 60.95,11.26 59.69,12.53 59.69,16.98 52.38,24.28 48.25,24.28 v41.91,30.63
  Bottom 0.254: JM1.14 37.14,41.11 v37.78,40.48 | v37.78,38.25 37.78,36.98 38.73,36.03 v38.73,35.4 | v40.32,33.81 40.32,32.86 41.91,31.27 v41.91,30.63
N$1  (via drill 0.3)
  Top 0.254: IC2.43 63.88,62.95 v64.45,62.38 | v64.45,56.03 65.4,55.08 68.89,55.08 | 68.89,55.08 Q1.2 | 68.89,55.08 C7.1
  Bottom 0.254: v64.45,56.03 v64.45,62.38
N$2  (via drill 0.3)
  Top 0.254: IC2.44 64.02,63.45 64.13,63.34 67.3,63.34 67.62,63.65 v68.89,63.65 | Q1.1 68.89,60.16 C8.1
  Bottom 0.254: v68.89,63.65 Q1.1
N$3
  Top 0.406: R3.1 59.69,82.38 58.41,83.66 57.14,83.66 57.14,83.98 X1.3
N$4
  Top 0.406: 57.14,78.57 R1.1 57.14,81.98 X1.2
N$5
  Top 0.254: IC2.6 58.66,68.35 59.37,69.05 59.37,70 C6.2
N$6
  Top 0.254: IC2.8 57.66,68.53 57.14,69.05 R1.2
N$7
  Top 0.254: IC2.7 58.16,70.39 58.41,70.64 R7.1 | R3.2 59.69,73.49 59.37,73.18 59.37,71.91 R7.1 | R7.1
N$8
  Top 0.254: IC2.5 59.16,68.21 59.37,68.41 60,68.41 60.32,68.73 60.32,71.91 R7.2
N$9
  Top 0.254: 65.4,66.19 R6.1 | IC2.46 63.66,64.45 64.45,65.24 65.4,65.24 65.4,66.19 | 65.4,66.19 C4.2
N$10  (via drill 0.3)
  Top 0.254: IC3.1 68.89,69.68 67.3,71.27 64.13,71.27 v62.86,70 | v62.86,66.83 62.86,65.88 62.91,65.82 IC2.48
  Bottom 0.254: v62.86,66.83 v62.86,70
N$11
  Top 0.254: IC3.2 68.58,68.41 67.94,69.05 63.81,69.05 61.96,67.2 IC2.1
N$12  (via drill 0.3)
  Top 0.254: 70.8,67.14 69.84,67.14 69.53,67.46 68.26,67.46 R9.2 | IC2.2 60.66,65.27 v60.64,65.24 | 70.8,67.14 IC3.3 | v73.34,67.14 70.8,67.14
  Bottom 0.254: v60.64,65.24 71.43,65.24 v73.34,67.14
N$13
  Top 0.254: R9.1 69.22,65.57 69.53,65.88 IC3.4 | IC3.4 71.11,65.88 | IC3.4 71.05,65.62 71.43,65.24 71.43,63.97 R8.1
N$14
  Top 0.305: R10.2 23.49,65.24 22.22,66.51 22.22,67.78 21.9,68.1 19.36,68.1 18.41,69.05 C10.2 | C10.2 | Q2.1 8.84,69.1 C10.2
N$16  (via drill 0.3)
  Top 0.254: IC6.21 48.91,47.76 46.03,50.63 41.91,50.63 40.95,49.68 v40.32,49.68 | v33.97,50 33.65,49.68 25.71,49.68 24.76,48.73 C40.1
  Bottom 0.254: v33.97,50 38.73,50 39.05,49.68 v40.32,49.68
N$17
  Top 0.305: IC1.1 18.69,74.09 19.36,74.77 20.63,74.77 R2.1 R4.2
N$18
  Top 0.254: S1.3 40.58,3.28 40.95,3.64 40.95,4.28 41.89,5.22 R19.2 R17.1 41.89,7.15 40.64,8.41 40.64,10.63 40.58,10.58 S1.4
N$19
  Top 0.254: S2.4 50.74,10.36 50.8,10.31 50.8,7.46 51.1,7.15 R18.1 R20.2 51.73,5.22 50.8,4.28 50.8,3.33 50.74,3.28 S2.3
N$20
  Top 0.254: IC6.22 48.41,47.62 46.03,50 41.91,50 40,48.09 38.41,48.09 37.78,47.46 C36.1
N$21
  Top 0.254: D3.1 R15.2
N$22
  Top 0.254: D4.1 R16.2
N$23
  Top 0.254: IC6.23 47.91,47.49 46.03,49.37 42.22,49.37 40.32,47.46 38.41,47.46 37.14,46.19 37.14,45.55 36.51,44.92 31.11,44.92 29.21,46.83 19.68,46.83 16.19,50.32 C39.1
N$24
  Top 0.254: IC6.24 47.25,45.61 46.03,46.83 38.73,46.83 37.78,45.87 37.78,44.6 36.83,43.65 36.83,42.7 36.51,42.38 29.84,42.38 29.21,41.75 25.08,41.75 21.27,45.55 C35.1
N$25
  Top 0.254: IC6.35 44.42,38.86 44.13,38.57 44.13,37.3 42.86,36.03 39.05,36.03 37.78,37.3 33.97,37.3 32.7,38.57 26.03,38.57 21.58,43.02 C38.1 17.14,43.02
N$26
  Top 0.254: C34.1 19.04,34.12 20.32,35.4 23.17,35.4 23.81,36.03 29.21,36.03 29.52,35.71 33.02,35.71 33.97,34.76 36.19,34.76 36.83,34.12 36.83,32.86 41.59,32.86 41.91,33.17 41.91,35.08 42.22,35.4 42.86,35.4 45.66,38.2 IC6.36
N$27
  Top 0.254: IC6.39 48.41,35.23 46.67,33.49 43.49,33.49 42.22,32.22 34.92,32.22 33.02,34.12 31.11,34.12 C37.1
N$28
  Top 0.254: IC6.41 49.41,35.6 46.67,32.86 43.81,32.86 42.54,31.59 36.83,31.59 36.83,30.32 36.19,29.68 34.92,29.68 34.28,30.32 34.28,32.22 33.65,32.86 29.84,32.86 29.21,33.49 27.93,33.49 27.62,33.81 27.75,33.94 C33.1
N$29
  Top 0.254: JP1.3 C33.2
N$30
  Top 0.254: C36.2 30.16,47.46 29.52,48.09 JP2.1
N$31
  Top 0.305: X10.R 12,34.07 12.06,34.12 C34.2 14.6,34.12 14.61,34.14 R39.2
N$32
  Top 0.305: R40.2 14.61,42.69 14.4,42.9 C38.2 10.47,43.02 10.5,43.04 X10.L
N$33
  Top 0.305: X9.L 10.5,57.01 10.47,56.99 10.48,56.97 R35.1
N$34
  Top 0.305: X9.R 11.74,48.09 R36.1
N$35
  Top 0.254: C37.2 26.22,37.11 24.13,39.2 JP1.1
N$36  (via drill 0.3)
  Top 0.254: v24.76,44.6 C40.2
  Bottom 0.254: v24.76,44.6 24.76,43.97 25.71,43.02 JP2.3
N$37
  Top 0.254: IC6.29 44.33,41.86 43.17,43.02 C41.1
N$38
  Top 0.254: IC6.30 44.38,41.36 44.13,41.11 C42.1
N$39
  Top 0.254: IC6.31 44.51,40.86 42.86,39.2 C43.1
N$40
  Top 0.254: IC6.32 44.65,40.36 43.49,39.2 43.49,37.62 43.17,37.3 C44.1
N$41
  Top 0.305: R23.2 21.6,29.67 | R21.1 31.12,30.94 30.16,31.9 27.62,31.9 27.3,31.59 27.3,30.63 R24.1 26.67,30.63 26.35,30.32 25.08,30.32 C18.2 23.79,30.3 23.17,29.68 R23.2 | R23.2
N$42
  Top 0.254: IC6.27 44.6,42.86 44.44,43.02 C46.1 44.44,45.55 C45.1
N$43
  Top 0.254: IC6.2 56.86,38.86 58.1,37.62 58.1,35.4 59.37,34.12 Q3.1 61.46,34.25 61.59,34.12 63.18,34.12 C47.1
N$44
  Top 0.254: IC6.3 59.21,39.36 59.37,39.2 Q3.2 60.83,39.08 61.27,39.52 62.86,39.52 62.87,39.51 C48.1
N$45
  Top 0.305: 20.63,68.73 R5.2 R4.1
N$46
  Top 0.305: C35.2 R37.2 R36.2 16.19,48.09 R36.2
N$47
  Top 0.305: C39.2 R35.2 13.66,55.09 R38.2
N$48  (via drill 0.3)
  Top 0.305: v23.81,25.55 23.79,25.57 C25.2 22.22,25.23 22.2,25.26 IC5.8 | v16.82,25.55 16.82,26.82 C24.2 16.82,27.46 15.87,26.51 14.92,26.51 14.6,26.19 14.6,23.65 14.28,23.33 R29.2 13.65,23.33 13.65,21.11 14.28,20.47 17.14,20.47 18.73,18.88 20.63,18.88 23.17,16.34 L2.1
  Bottom 0.305: v23.81,25.55 20,25.55 19.36,24.92 17.46,24.92 v16.82,25.55
N$56  (via drill 0.3)
  other vias: 93.02,60.48
N$59  (via drill 0.3)
  other vias: 98.74,71.91
N$60
  Top 0.305: SJ2.3 32.7,25.87 32.7,26.82 32.06,27.46 32.06,28.41 R22.1 C19.2 | C19.2 28.57,28.41 28.25,28.09 28.25,27.14 27.3,26.19 24.76,26.19 24.44,26.51 18.41,26.51 18.21,26.31 IC5.1 | R24.2 29.19,28.42 C19.2
N$62
  Top 0.305: 27.3,23.33 26.67,23.33 26.35,23.01 25.39,23.01 C22.2 25.38,23 25.08,22.7 22.23,22.68 22.22,23.01 R27.2 | R25.1 31.12,23.63 30.16,24.6 27.62,24.6 27.3,24.28 27.3,23.33 | 27.3,23.33 R28.1
N$63
  Top 0.305: R31.2 48.25,19.52 48.24,19.53 C28.2 47.3,21.74 47.3,20.79 46.98,20.47 46.98,18.88 44.76,18.88 38.73,12.85 33.97,12.85 31.43,10.31 R32.1 29.84,10.31
N$64  (via drill 0.3)
  Top 0.305: 17.46,15.08 C27.2 18.41,15.08 19.68,13.8 19.68,12.53 23.49,8.72 v24.44,8.72 | R32.2 C29.2 v26.33,8.74 v26.35,8.72
  Bottom 0.305: v24.44,8.72 v26.35,8.72
N$65
  Top 0.305: X8.L 10.5,15.1 10.47,15.08 C27.1
N$66
  Top 0.305: X8.R 11.74,6.19 C30.1
N$67
  Top 0.305: 17.46,6.19 C30.2 23.81,6.19 25.39,7.77 25.39,12.53 C32.2 R34.2
N$68
  Top 0.305: C31.2 43.81,19.84 43.82,19.83 | 43.82,19.83 R33.2 | 43.82,19.83 43.82,18.9 38.41,13.49 32.7,13.49 31.75,12.53 R34.1
N$69
  Top 0.305: SJ3.3 32.7,18.25 32.7,19.2 32.06,19.84 32.06,20.79 R26.1 C23.2 | 29.19,22.06 29.19,20.8 C23.2 | 29.19,22.06 R28.2 | C23.2 | IC5.3 17.46,23.96 17.14,23.65 17.14,22.7 18.41,21.42 20.63,21.42 21.27,22.06 29.19,22.06 | 29.19,22.06 29.21,22.06
N$70
  Top 0.305: C20.1 R23.1
N$71
  Top 0.305: C21.1 20.52,20.36 21.27,21.11 22.22,21.11 R27.1
N$87
  Top 0.305: D2.1 20.96,56.34 21.27,56.03 21.27,54.76 21.58,54.45 22.54,54.45 22.55,54.46 R13.1
N$88
  Top 0.254: R14.2 R12.1
N$91
  Top 0.254: R11.1 R12.2 20.64,85.23 20.63,85.24
  Top 0.305: IC4.1 19.72,86.16 20.63,85.24
N$92
  Top 0.61: X3.1 27.93,90.32 27.62,90.64 D1.1 26.02,92.88 LSP1.MP
N$94
  Top 0.305: X4.1 75.79,84.2 77.15,85.56 X4.6 77.16,85.57 78.42,86.83 83.18,86.83 84.13,85.88 84.13,83.34 83.81,83.02 X4.4
NCTS  (via drill 0.3)
  Top 0.305: v79.37,79.53 75.24,75.4 72.38,75.4 JM1.71
  Bottom 0.305: X4.7 79.9,80.06 v79.37,79.53
NRTS
  Top 0.305: JM1.69 69.84,77.94 75.24,77.94 79.69,82.38 79.69,83.34 80.64,84.29 81.59,84.29 82.86,85.56 X4.8
PHD  (via drill 0.3)
  Top 0.254: v37.46,48.41 v39.68,50.63 | v54.92,50 v57.78,50 | v69.53,42.38 v82.86,42.38 | v87.94,42.38 89.85,40.48 96.2,40.48 97.47,39.2 101.59,39.2 103.82,41.43 JP3.1
  Bottom 0.254: JM1.12 35.87,46.19 37.46,47.78 v37.46,48.41 | v39.68,50.63 47.3,50.63 47.94,50 v54.92,50 | v57.78,50 61.27,50 68.89,42.38 v69.53,42.38 | v82.86,42.38 v87.94,42.38
RXD
  Top 0.305: JM1.70 68.58,74.77 70.48,76.67 74.92,76.67 X4.3
SDIL
  Top 0.305: SJ2.2 31.11,24.92 31.43,24.6 34.28,24.6 JM1.20
SDIR
  Top 0.305: 35.56,17.62 JM1.23 34.28,16.98 31.43,16.98 31.11,17.3 SJ3.2
SDOL  (via drill 0.3)
  Top 0.254: R21.2 32.7,30.32
  Top 0.305: R21.2 v33.02,31.9
  Bottom 0.305: JM1.18 33.97,30.95 v33.02,31.9
SDOL2
  Top 0.305: R22.2 JM1.19
SDOR
  Top 0.305: R25.2 JM1.21
SDOR2
  Top 0.305: R26.2 JM1.22
T1  (via drill 0.3)
  Top 0.254: JM1.61 45.72,76.03 v43.81,77.94 | v43.81,80.16 43.81,85.88 41.91,87.78 SV6.3
  Bottom 0.254: v43.81,77.94 v43.81,80.16
T2  (via drill 0.3)
  Top 0.254: JM1.62 48.25,74.77 v45.08,77.94 | v45.08,80.16 45.08,86.19 43.17,88.1 43.17,91.91 SV6.4
  Bottom 0.254: v45.08,77.94 v45.08,80.16
T3  (via drill 0.3)
  Top 0.254: JM1.63 47.62,77.3 46.98,77.3 v46.35,77.94 | v46.35,80.16 46.35,86.51 44.44,88.42 SV6.5
  Bottom 0.254: v46.35,77.94 v46.35,80.16
T4
  Top 0.254: JM1.65 55.88,86.51 53.02,89.37 46.35,89.37 45.72,90 45.72,91.91 SV6.6
T5
  Top 0.254: JM1.66 58.41,77.94 60.64,77.94 61.27,78.57 61.27,83.02 53.65,90.64 SV6.7
T6
  Top 0.254: JM1.67 60.95,76.03 64.77,79.84 64.77,89.05 60.64,93.18 SV6.8
TCK  (via drill 0.3)
  Top 0.254: IC2.24 52.81,59.95 52.06,59.21 v49.21,59.21 | v41.27,68.73 41.27,69.37 37.78,72.86 25.39,72.86 X2.1
  Bottom 0.254: v49.21,59.21 49.21,60.48 47.62,62.07 42.54,62.07 41.27,63.34 v41.27,68.73
TDI  (via drill 0.3)
  Top 0.254: v41.59,60.48 37.46,60.48 37.14,60.16 27.93,60.16 X2.9 | IC2.23 47.97,60.45 v47.94,60.48
  Bottom 0.254: v41.59,60.48 v47.94,60.48
TDO
  Top 0.254: IC2.22 50,60.95 45.08,65.88 42.22,65.88 37.78,70.32 25.39,70.32 X2.3
TMS  (via drill 0.3)
  Top 0.254: IC2.21 50.77,61.45 v47.94,64.29 | v44.44,64.29 41.27,64.29 37.78,67.78 25.39,67.78 X2.5
  Bottom 0.254: v44.44,64.29 v47.94,64.29
TXD
  Top 0.305: JM1.68 68.58,79.21 74.61,79.21 78.42,83.02 X4.2
USB_D0  (via drill 0.3)
  Top 0.254: IC2.40 65.1,61.45 66.35,62.7 75.24,62.7 v75.88,63.34 | v75.88,71.59 JM1.38
  Bottom 0.254: v75.88,63.34 v75.88,71.59
USB_D1
  Top 0.254: IC2.39 65.55,60.95 66.67,62.07 75.88,62.07 77.15,63.34 77.15,63.97 80,66.83 80,67.78 JM1.39
USB_D2
  Top 0.254: IC2.38 66.01,60.45 66.99,61.43 75.88,61.43 77.78,63.34 77.78,63.97 80.32,66.51 JM1.40
USB_D3
  Top 0.254: IC2.37 65.29,59.95 66.99,58.26 75.88,58.26 78.1,60.48 78.1,62.07 80,63.97 JM1.41
USB_D4
  Top 0.254: IC2.36 62.6,58.2 63.18,57.62 76.19,57.62 80,61.43 JM1.42
USB_D5
  Top 0.254: IC2.35 60.66,57.27 60.95,56.99 78.1,56.99 80,58.89 JM1.43
USB_D6
  Top 0.254: IC2.33 59.66,55.73 61.59,53.81 JM1.45
USB_D7
  Top 0.254: IC2.32 59.16,55.28 63.18,51.27 JM1.46
USB_NPWR  (via drill 0.3)
  Top 0.254: v57.14,61.43 53.97,58.26 v49.84,58.26 | IC2.41 60.52,61.95 v60,61.43 | R10.1 38.09,65.24 40.64,62.7 45.08,62.7 45.72,62.07 v45.72,58.26
  Bottom 0.254: v57.14,61.43 v60,61.43 | v45.72,58.26 v49.84,58.26
USB_NRD
  Top 0.254: IC2.28 57.16,54.43 67.94,43.65 JM1.49
USB_NRXF
  Top 0.254: IC2.30 58.16,55.33 64.77,48.73 JM1.47
USB_NSI
  Top 0.254: IC2.26 56.16,53.52 71.11,38.57 JM1.51
USB_NTXE
  Top 0.254: IC2.29 57.66,54.88 66.35,46.19 JM1.48
USB_WR
  Top 0.254: IC2.27 56.66,53.97 69.53,41.11 JM1.50
VCC  (via drill 0.3)
  Top 0.254: C17.2 22.54,63.02 21.92,63.64 21.92,63.66 v21.9,64.92 | v21.9,69.05 21.9,70.32 | 53.02,42.36 53,42.36 52.38,41.75 52.38,39.52 53.55,38.36 IC6.1 54.66,37.04 54.61,36.98 55.56,36.03 55.56,32.86 54.29,31.59 L3.1 | 53.02,42.36 IC6.9 | v54.61,44.92 53.97,44.92 53.02,43.97 53.02,42.36 | v57.46,47.46 57.46,47.78 58.73,49.05 58.73,50.32 55.56,53.49 55.56,55.72 53.65,55.72 | C51.2 60.02,45.23 59.37,45.87 60.64,47.14 | C52.2 66.99,39.52 67.62,40.16 | v51.75,8.09 54.29,8.09 55.56,9.36 61.91,9.36 62.22,9.04 63.49,9.04 C53.1 64.44,9.03 64.77,9.36 SV2.2 | SV6.2 39.68,93.18 40.64,92.23 v40.64,80.16 | 53.65,55.72 53.65,57.3 | 53.65,55.72 C15.2
  Top 0.305: R13.2 22.86,58.57 | v40.64,75.08 v40.64,77.94 | S1.2 32.91,10.53 31.11,8.72 29.52,8.72 29.21,9.04 29.21,15.71 28.57,16.34 L2.2
  Top 0.406: v50.16,22.06 50.16,16.98 49.52,16.34 49.52,13.8 46.03,10.31 45.82,10.53 S2.2
  Top 0.61: JM1.1 38.09,74.13 v40.32,71.91 | X6.4 84.92,57.46 85.08,57.3 v90.16,57.3 v97.78,57.3 | X5.4 90.01,25.71 90.16,25.87 v90.16,37.3 | v90.16,42.06 C14.2 | 5.07,60.48 SJ1.2 SV1.2 | 22.86,58.57 26.35,58.57 26.35,55.72 C13.+ | 58.73,49.05 60.64,47.14 67.62,40.16 v70.48,37.3 | v40.32,58.57 40.32,57.3 v42.22,57.3 | 53.65,57.3 v50.8,57.3 | L3.1 52.37,27.45 v50.16,25.23 | v97.78,67.46 97.78,69.05 103.18,74.45 103.18,82.07 C16.2 103.19,83.96 LSP2.MP
  Bottom 0.254: v21.9,64.92 v21.9,69.05 | v57.46,47.46 57.14,47.46 v54.61,44.92 | v51.75,8.09 48.25,8.09 45.77,10.58 | 45.77,10.58 45.72,10.63 | S2.2 45.77,10.58
  Bottom 0.305: v40.64,77.94 v40.64,80.16 | v40.64,75.08 40.64,72.22 v40.32,71.91
  Bottom 0.61: v70.48,37.3 v90.16,37.3 v90.16,42.06 v90.16,57.3 | X2.6 X2.4 30.47,71.59 33.02,74.13 JM1.1 | v40.32,58.57 v40.32,71.91 | v50.8,57.3 v42.22,57.3 | v50.16,22.06 v50.16,25.23 | v97.78,57.3 v97.78,67.46 | S1.1 35.61,4.23 35.56,4.28 35.56,6.82 | S1.2 35.61,6.87 35.56,6.82 | 35.56,6.82 45.72,6.82 | S2.1 45.77,3.28 45.72,3.33 45.72,6.82 | S2.2 45.77,10.36 45.72,10.31 45.72,6.82
  pour Top (isolate 0.254): 1.27,62.07 1.27,59.52 19.04,59.52 19.04,51.27 43.17,51.27 43.17,77.3 20.95,77.3 20.95,62.07
  pour Top (isolate 0.254): 48.57,57.62 56.19,57.62 56.19,53.49 71.11,38.57 71.11,35.71 65.08,29.68 51.43,29.68 51.43,42.06 54.61,45.24 54.61,48.09 48.57,54.13
VCCEXT
  Top 0.254: C12.2 38.41,83.97 38.09,84.29 26.67,84.29
  Top 0.61: C11.+ 26.67,81.75 26.67,84.29 24.13,86.83 D1.2 17.46,90.64 17.43,90.66 IC4.3
VCCEXT3V3  (via drill 0.3)
  Top 0.254: R11.2 20.01,89.04 20,89.05
  Top 0.305: 20,89.05 19.39,88.44 IC4.2 17.17,88.44 17.14,88.42 v15.24,88.42 | IC4.4 v13.33,88.42
  Top 0.61: v8.89,88.42 IC4.4 | v8.89,88.42 v8.89,89.69 v8.89,90.96 v8.89,92.23 8.89,92.86 v9.84,92.86 v11.11,92.86 v12.38,92.86 v13.65,92.86 14.28,92.86 | v8.89,84.61 8.89,83.97 v9.84,83.97 v11.11,83.97 v12.38,83.97 v13.65,83.97 14.28,83.97 | v8.89,84.61 v8.89,85.88 v8.89,87.15 v8.89,88.42 | v8.89,84.61 8.57,84.29 2.54,84.29 SV1.1 2.54,63.34 3.49,62.38 3.49,60.79 SJ1.3
  Bottom 0.305: v13.33,88.42 v15.24,88.42
  pour Top (isolate 0.254): 15.55,95.08 15.55,83.02 0.63,83.02 0.63,95.08
  pour Bottom (isolate 0.254): 0.63,95.08 19.36,95.08 19.36,83.02 0.63,83.02
VCCUSB
  Top 0.305: 53.33,78.57 L1.2
  Top 0.406: X1.1 54.62,81.77 53.33,80.48 53.33,78.57 54.29,78.57 54.61,78.26 54.61,76.67 54.29,76.35 C1.2
VCCUSB3V3  (via drill 0.3)
  Top 0.254: IC2.10 56.66,65.08 56.51,64.92 | 56.51,64.92 56.48,64.95 IC2.14 51.46,64.95 51.43,64.92 51.44,64.91 C5.2 | IC2.31 58.66,61.82 56.51,63.97 56.51,64.92
  Top 0.305: R2.2 19.04,76.67 18.75,76.38 IC1.2 15.26,76.38 v15.24,76.35 | 11.11,76.35 IC1.4 v13.33,76.35
  Top 0.406: R2.2 37.79,76.66 49.52,64.92 51.75,64.92 C5.2 | v12.06,66.83 12.38,66.51 12.38,64.92 C3.+
  Top 0.61: v8.89,76.35 IC1.4 | v8.89,76.35 v8.89,77.62 v8.89,78.89 v8.89,80.16 8.89,80.48 v10.16,80.48 v11.43,80.48 v12.7,80.48 v13.96,80.48 14.28,80.48 | v8.89,72.54 8.89,72.22 v10.16,72.22 | v8.89,72.54 v8.89,73.81 v8.89,75.08 v8.89,76.35 | v10.16,72.22 v11.43,72.22 v12.7,72.22 v13.96,72.22 14.28,72.22 | v10.16,72.22 9.52,71.59 | Q2.2 4.44,72.23 4.76,72.54 v8.89,72.54
  Bottom 0.305: v13.33,76.35 v15.24,76.35
  Bottom 0.61: v12.06,66.83 12.06,72.22 v11.43,72.22
  pour Top (isolate 0.254): 15.87,81.75 3.8,81.75 3.8,70.95 15.87,70.95
  pour Bottom (isolate 0.254): 19.04,81.75 0.63,81.75 0.63,70.95 19.04,70.95
VCCUSB3V3SW
  Top 0.61: Q2.3 8.84,67.1 8.89,67.14 | 8.89,67.14 C10.1 | 8.89,67.14 8.89,65.88 7.62,64.6 SV1.3 7.62,63.34 6.66,62.38 6.66,61.11 6.6,61.05 SJ1.1
VREF
  Top 0.305: IC5.4 19.02,23.31 19.36,23.65 19.36,24.28 19.04,24.61 IC5.2 17.15,24.61 16.82,24.28 16.5,24.28 | C26.2 15.55,25.23 16.5,24.28 | 15.55,23.33 16.19,23.33 16.5,23.65 16.5,24.28 | 15.55,23.33 R29.1 | R30.2 15.55,23.33

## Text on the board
Top: 3V3 | GND | dspio200510
Bottom: www.soc.tuwien.ac.at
